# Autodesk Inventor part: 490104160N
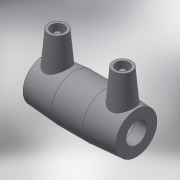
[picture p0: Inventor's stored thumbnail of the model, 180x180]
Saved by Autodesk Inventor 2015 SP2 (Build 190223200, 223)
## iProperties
Created: 2017-06
Part Number: 490104160N
Material: Generic
Description: PLASSON COUPLER 160-160
Document SubType Name: Modeling
Designer: KIM
Mass: 55.0731 g
Surface Area: 148.067 cm^2
Volume: 55.0731 cm^3
Density: 1 g/cm^3
Appearance: Default
Author: KIM
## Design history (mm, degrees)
derived "490104.ipt"
feature "Solid1::490104.ipt"
tag "TaggingFeature1"
body "Solid1"
other parameters: "d0" = 195, "d2" = 194, "d3" = 93, "d4" = 65, "d5" = 174.6, "d6" = 152, "d8" = 168 deg, "d10" = 37.2, "d11" = 12.4, "d13" = 195, "d14" = 17.6296, "d15" = 93, "d16" = 93, "d17" = 152, "d19" = 3.52592, "d20" = 168 deg, "d22" = 182.36, "d23" = 194, "d24" = 176.8892, "d25" = 135 deg, "d26" = 78, "d27" = 135 deg, "d29" = 105, "d30" = 14, "d31" = 68.25, "d34" = 5 deg, "d35" = 15, "d39" = 5 deg, "d41" = 4, "d42" = 14, "d43" = 0, "d45" = 4, "d46" = 14, "d47" = 0, "d48" = 3, "d49" = 0, "d50" = 3, "d51" = 0, "d52" = 26.97, "d53" = 6.7425, "L_" = 195, "L_1" = 93, "D_" = 194, "A_" = 105, "d_2" = 12
